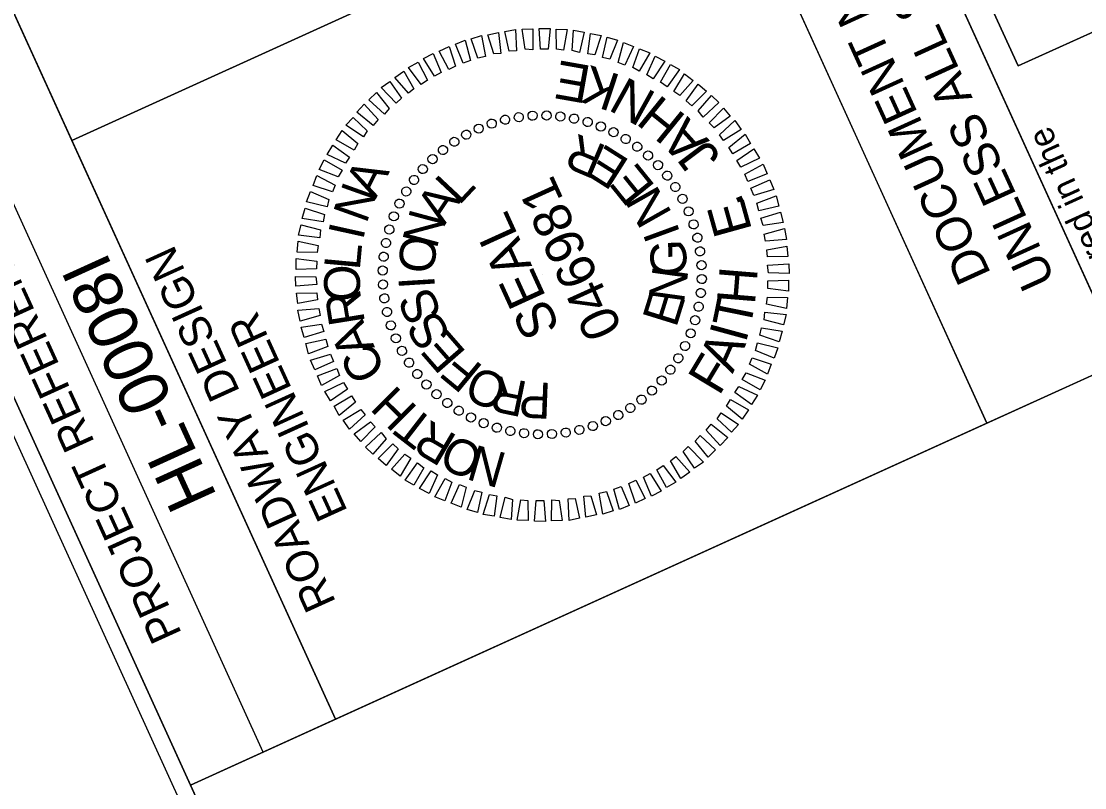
# Model space of a CAD drawing. Extents: x 2097304 to 2099003, y 683920 to 685908.
# Drawn here: x 2097390.4 to 2097557.6, y 685265 to 685385.6 of the extents above; entities that cross this region are included whole.
import ezdxf

# ---------------------------------------------------------------- set-up
doc = ezdxf.new("R2010")
doc.units = 0
for name, color, linetype in [('Sheet Block Title CELL', 7, 'Continuous'), ('Sheet Data Field CELL', 7, 'Continuous'), ('Sheet Layout Plan Border', 7, 'Continuous'), ('Sheet PE Seal Cell', 7, 'Continuous'), ('Sheet Plot Border Inside CELL', 7, 'Continuous'), ('Sheet Profile CELL', 7, 'Continuous'), ('Sheet Sticker Exception Certification CELL', 7, 'Continuous')]:
    doc.layers.add(name, color=color, linetype=linetype)

msp = doc.modelspace()

# ---------------------------------------------------------------- linework, layer by layer
at = {"layer": 'Sheet Block Title CELL'}
for points in [[(2097563.62, 685332.14), (2097480.76, 685514.24), (2097504.66, 685525.11), (2097587.51, 685343.02)], [(2097547.11, 685378.58), (2097538.59, 685397.29), (2097554.83, 685404.68), (2097563.35, 685385.97)]]:
    msp.add_lwpolyline(points, close=True, dxfattribs=at)
msp.add_lwpolyline([(2097538.59, 685397.29), (2097547.11, 685378.58), (2097563.35, 685385.97), (2097554.83, 685404.68), (2097538.59, 685397.29)], dxfattribs=at)
at = {"layer": 'Sheet Layout Plan Border'}
msp.add_lwpolyline([(2098911.14, 684517.12), (2097955.44, 684082.23), (2097417.03, 685265.44), (2097587.51, 685343.02), (2097536.86, 685454.34), (2098323.16, 685809.28)], close=True, dxfattribs=at)
at = {"layer": 'Sheet PE Seal Cell'}
for p, q in [((2097468.61, 685370.57), (2097468.61, 685370.57)), ((2097470.81, 685370.8), (2097470.81, 685370.8)), ((2097473, 685370.81), (2097473, 685370.81)), ((2097475.19, 685370.7), (2097475.19, 685370.7)), ((2097477.35, 685370.31), (2097477.35, 685370.31)), ((2097462.34, 685368.76), (2097462.34, 685368.76)), ((2097464.41, 685369.53), (2097464.41, 685369.53)), ((2097466.51, 685370.1), (2097466.51, 685370.1)), ((2097479.5, 685369.81), (2097479.5, 685369.81)), ((2097481.53, 685369.08), (2097481.53, 685369.08)), ((2097460.36, 685367.8), (2097460.36, 685367.8)), ((2097483.58, 685368.2), (2097483.58, 685368.2)), ((2097485.44, 685367.13), (2097485.44, 685367.13)), ((2097456.69, 685365.36), (2097456.69, 685365.36)), ((2097458.53, 685366.64), (2097458.53, 685366.64)), ((2097487.28, 685365.88), (2097487.28, 685365.88)), ((2097455.03, 685363.95), (2097455.03, 685363.95)), ((2097488.99, 685364.52), (2097488.99, 685364.52)), ((2097453.54, 685362.39), (2097453.54, 685362.39)), ((2097490.55, 685363.03), (2097490.55, 685363.03)), ((2097452.18, 685360.67), (2097452.18, 685360.67)), ((2097491.97, 685361.36), (2097491.97, 685361.36)), ((2097450.93, 685358.84), (2097450.93, 685358.84)), ((2097493.24, 685359.53), (2097493.24, 685359.53)), ((2097449.85, 685356.98), (2097449.85, 685356.98)), ((2097494.41, 685357.69), (2097494.41, 685357.69)), ((2097495.36, 685355.71), (2097495.36, 685355.71)), ((2097448.97, 685354.93), (2097448.97, 685354.93)), ((2097496.14, 685353.65), (2097496.14, 685353.65)), ((2097448.25, 685352.9), (2097448.25, 685352.9)), ((2097447.74, 685350.74), (2097447.74, 685350.74)), ((2097496.71, 685351.55), (2097496.71, 685351.55)), ((2097447.35, 685348.59), (2097447.35, 685348.59)), ((2097497.17, 685349.45), (2097497.17, 685349.45)), ((2097497.4, 685347.25), (2097497.4, 685347.25)), ((2097447.25, 685346.4), (2097447.25, 685346.4)), ((2097472.33, 685345.73), (2097472.33, 685345.73)), ((2097447.26, 685344.21), (2097447.26, 685344.21)), ((2097497.41, 685345.05), (2097497.41, 685345.05)), ((2097447.49, 685342), (2097447.49, 685342)), ((2097497.31, 685342.86), (2097497.31, 685342.86)), ((2097496.92, 685340.71), (2097496.92, 685340.71)), ((2097447.95, 685339.91), (2097447.95, 685339.91)), ((2097496.41, 685338.56), (2097496.41, 685338.56)), ((2097448.52, 685337.8), (2097448.52, 685337.8)), ((2097449.3, 685335.74), (2097449.3, 685335.74)), ((2097495.69, 685336.52), (2097495.69, 685336.52)), ((2097450.25, 685333.76), (2097450.25, 685333.76)), ((2097494.81, 685334.48), (2097494.81, 685334.48)), ((2097451.42, 685331.93), (2097451.42, 685331.93)), ((2097493.73, 685332.61), (2097493.73, 685332.61)), ((2097492.48, 685330.78), (2097492.48, 685330.78)), ((2097452.69, 685330.09), (2097452.69, 685330.09)), ((2097491.12, 685329.06), (2097491.12, 685329.06)), ((2097454.11, 685328.43), (2097454.11, 685328.43)), ((2097455.67, 685326.94), (2097455.67, 685326.94)), ((2097489.63, 685327.51), (2097489.63, 685327.51)), ((2097457.38, 685325.58), (2097457.38, 685325.58)), ((2097487.97, 685326.09), (2097487.97, 685326.09)), ((2097459.22, 685324.32), (2097459.22, 685324.32)), ((2097484.3, 685323.65), (2097484.3, 685323.65)), ((2097486.13, 685324.81), (2097486.13, 685324.81)), ((2097461.08, 685323.25), (2097461.08, 685323.25)), ((2097463.13, 685322.37), (2097463.13, 685322.37)), ((2097480.25, 685321.92), (2097480.25, 685321.92)), ((2097482.32, 685322.69), (2097482.32, 685322.69)), ((2097465.16, 685321.64), (2097465.16, 685321.64)), ((2097467.31, 685321.14), (2097467.31, 685321.14)), ((2097469.47, 685320.75), (2097469.47, 685320.75)), ((2097471.66, 685320.65), (2097471.66, 685320.65)), ((2097473.85, 685320.65), (2097473.85, 685320.65)), ((2097476.05, 685320.89), (2097476.05, 685320.89)), ((2097478.15, 685321.35), (2097478.15, 685321.35))]:
    msp.add_line(p, q, dxfattribs=at)
for points in [[(2097464.7, 685380.49), (2097463.78, 685383.47), (2097465.47, 685383.86), (2097465.82, 685380.56)], [(2097467.15, 685380.89), (2097466.46, 685383.98), (2097468.11, 685384.34), (2097468.27, 685380.96)], [(2097469.65, 685381.2), (2097469.18, 685384.39), (2097470.86, 685384.44), (2097470.83, 685381.13)], [(2097472.06, 685381.2), (2097471.83, 685384.5), (2097473.55, 685384.46), (2097473.27, 685381.2)], [(2097474.57, 685381.24), (2097474.53, 685384.36), (2097476.25, 685384.31), (2097475.68, 685381.09)], [(2097477.02, 685381.04), (2097477.23, 685384.21), (2097478.92, 685383.88), (2097478.18, 685380.69)], [(2097479.47, 685380.5), (2097479.9, 685383.67), (2097481.61, 685383.4), (2097480.6, 685380.31)], [(2097459.92, 685379.03), (2097458.67, 685382.03), (2097460.21, 685382.62), (2097461.06, 685379.43)], [(2097462.21, 685379.79), (2097461.16, 685382.83), (2097462.79, 685383.35), (2097463.41, 685380.06)], [(2097481.82, 685379.93), (2097482.51, 685383.1), (2097484.15, 685382.64), (2097482.93, 685379.66)], [(2097484.27, 685379.12), (2097485.08, 685382.29), (2097486.65, 685381.63), (2097485.33, 685378.72)], [(2097455.37, 685376.96), (2097453.66, 685379.75), (2097455.17, 685380.54), (2097456.42, 685377.55)], [(2097457.63, 685378.04), (2097456.14, 685380.93), (2097457.69, 685381.64), (2097458.72, 685378.54)], [(2097486.55, 685378.34), (2097487.64, 685381.26), (2097489.23, 685380.66), (2097487.58, 685377.77)], [(2097453.31, 685375.69), (2097451.33, 685378.36), (2097452.81, 685379.2), (2097454.32, 685376.37)], [(2097488.79, 685377.17), (2097490.08, 685380.12), (2097491.6, 685379.32), (2097489.77, 685376.57)], [(2097490.94, 685376.06), (2097492.49, 685378.8), (2097493.9, 685378.01), (2097491.94, 685375.3)], [(2097451.31, 685374.29), (2097449.14, 685376.76), (2097450.57, 685377.74), (2097452.15, 685374.99)], [(2097492.99, 685374.57), (2097494.68, 685377.37), (2097496.05, 685376.3), (2097493.93, 685373.96)], [(2097449.38, 685372.75), (2097447.01, 685375.18), (2097448.38, 685376.14), (2097450.19, 685373.5)], [(2097494.97, 685373.11), (2097496.86, 685375.73), (2097498.14, 685374.61), (2097495.84, 685372.3)], [(2097447.52, 685371.02), (2097445.08, 685373.26), (2097446.26, 685374.4), (2097448.27, 685371.91)], [(2097496.84, 685371.54), (2097498.94, 685373.93), (2097500.11, 685372.81), (2097497.63, 685370.53)], [(2097445.76, 685369.23), (2097443.17, 685371.3), (2097444.36, 685372.55), (2097446.55, 685370.14)], [(2097444.22, 685367.43), (2097441.46, 685369.25), (2097442.6, 685370.49), (2097444.83, 685368.37)], [(2097498.58, 685369.65), (2097500.83, 685371.94), (2097501.89, 685370.71), (2097499.33, 685368.84)], [(2097500.17, 685367.73), (2097502.6, 685369.99), (2097503.62, 685368.59), (2097500.83, 685366.88)], [(2097442.75, 685365.34), (2097439.92, 685366.96), (2097440.9, 685368.45), (2097443.37, 685366.39)], [(2097501.66, 685365.77), (2097504.24, 685367.83), (2097505.06, 685366.39), (2097502.29, 685364.74)], [(2097441.42, 685363.3), (2097438.5, 685364.66), (2097439.42, 685366.13), (2097442.04, 685364.24)], [(2097502.93, 685363.71), (2097505.61, 685365.54), (2097506.5, 685364.08), (2097503.56, 685362.68)], [(2097440.27, 685361.13), (2097437.27, 685362.29), (2097438.06, 685363.81), (2097440.89, 685362.18)], [(2097504.19, 685361.54), (2097507.05, 685363.12), (2097507.68, 685361.59), (2097504.64, 685360.43)], [(2097439.36, 685358.79), (2097436.33, 685359.78), (2097436.92, 685361.37), (2097439.77, 685359.81)], [(2097505.14, 685359.34), (2097508.1, 685360.68), (2097508.73, 685359.16), (2097505.59, 685358.22)], [(2097438.51, 685356.43), (2097435.29, 685357.22), (2097435.89, 685358.81), (2097438.8, 685357.6)], [(2097506.04, 685357), (2097509.08, 685358.16), (2097509.49, 685356.54), (2097506.35, 685355.82)], [(2097437.89, 685354.06), (2097434.62, 685354.6), (2097435.08, 685356.24), (2097438.13, 685355.21)], [(2097506.67, 685354.65), (2097509.77, 685355.57), (2097510.22, 685353.96), (2097507.03, 685353.49)], [(2097437.37, 685351.57), (2097434.01, 685351.96), (2097434.42, 685353.58), (2097437.46, 685352.82)], [(2097507.22, 685352.1), (2097510.39, 685352.99), (2097510.73, 685351.28), (2097507.43, 685351.04)], [(2097436.95, 685349.24), (2097433.8, 685349.29), (2097433.95, 685351), (2097437.1, 685350.35)], [(2097507.63, 685349.65), (2097510.76, 685350.25), (2097510.94, 685348.63), (2097507.74, 685348.55)], [(2097436.85, 685346.67), (2097433.65, 685346.58), (2097433.65, 685348.28), (2097436.9, 685347.9)], [(2097507.74, 685347.23), (2097511.08, 685347.48), (2097511.12, 685345.96), (2097507.9, 685346.03)], [(2097436.92, 685344.23), (2097433.58, 685343.97), (2097433.54, 685345.49), (2097436.76, 685345.42)], [(2097507.81, 685344.78), (2097511.01, 685344.87), (2097511.01, 685343.17), (2097507.76, 685343.56)], [(2097437.03, 685341.81), (2097433.9, 685341.2), (2097433.72, 685342.82), (2097436.92, 685342.91)], [(2097507.71, 685342.21), (2097510.86, 685342.17), (2097510.71, 685340.45), (2097507.56, 685341.1)], [(2097437.44, 685339.35), (2097434.27, 685338.46), (2097433.93, 685340.17), (2097437.23, 685340.41)], [(2097507.29, 685339.88), (2097510.65, 685339.49), (2097510.24, 685337.87), (2097507.2, 685338.63)], [(2097437.99, 685336.8), (2097434.89, 685335.89), (2097434.44, 685337.49), (2097437.63, 685337.96)], [(2097506.77, 685337.39), (2097510.04, 685336.85), (2097509.58, 685335.21), (2097506.53, 685336.24)], [(2097438.62, 685334.45), (2097435.58, 685333.29), (2097435.17, 685334.91), (2097438.31, 685335.63)], [(2097506.15, 685335.02), (2097509.37, 685334.23), (2097508.77, 685332.64), (2097505.86, 685333.85)], [(2097439.52, 685332.12), (2097436.56, 685330.77), (2097435.92, 685332.29), (2097439.07, 685333.23)], [(2097505.3, 685332.66), (2097508.33, 685331.68), (2097507.74, 685330.09), (2097504.89, 685331.65)], [(2097440.47, 685329.91), (2097437.61, 685328.34), (2097436.98, 685329.86), (2097440.02, 685331.02)], [(2097504.39, 685330.32), (2097507.39, 685329.16), (2097506.6, 685327.64), (2097503.77, 685329.27)], [(2097441.73, 685327.74), (2097439.05, 685325.91), (2097438.16, 685327.38), (2097441.1, 685328.77)], [(2097503.24, 685328.15), (2097506.16, 685326.79), (2097505.24, 685325.32), (2097502.62, 685327.21)], [(2097443, 685325.68), (2097440.42, 685323.62), (2097439.6, 685325.06), (2097442.37, 685326.71)], [(2097501.91, 685326.12), (2097504.74, 685324.49), (2097503.76, 685323), (2097501.29, 685325.06)], [(2097444.49, 685323.72), (2097442.06, 685321.46), (2097441.04, 685322.86), (2097443.83, 685324.57)], [(2097500.44, 685324.02), (2097503.2, 685322.2), (2097502.06, 685320.96), (2097499.83, 685323.08)], [(2097446.08, 685321.81), (2097443.83, 685319.52), (2097442.77, 685320.74), (2097445.33, 685322.62)], [(2097498.9, 685322.22), (2097501.49, 685320.16), (2097500.3, 685318.9), (2097498.11, 685321.31)], [(2097447.82, 685319.91), (2097445.72, 685317.52), (2097444.55, 685318.64), (2097447.03, 685320.92)], [(2097497.14, 685320.43), (2097499.58, 685318.19), (2097498.4, 685317.05), (2097496.39, 685319.54)], [(2097449.69, 685318.34), (2097447.8, 685315.72), (2097446.52, 685316.84), (2097448.82, 685319.15)], [(2097495.28, 685318.71), (2097497.65, 685316.27), (2097496.28, 685315.31), (2097494.47, 685317.95)], [(2097451.67, 685316.88), (2097449.98, 685314.08), (2097448.61, 685315.16), (2097450.73, 685317.5)], [(2097493.35, 685317.17), (2097495.52, 685314.69), (2097494.09, 685313.71), (2097492.51, 685316.46)], [(2097453.72, 685315.39), (2097452.17, 685312.65), (2097450.76, 685313.44), (2097452.72, 685316.15)], [(2097491.35, 685315.76), (2097493.33, 685313.09), (2097491.85, 685312.25), (2097490.34, 685315.08)], [(2097455.87, 685314.29), (2097454.58, 685311.34), (2097453.06, 685312.13), (2097454.89, 685314.88)], [(2097458.11, 685313.11), (2097457.02, 685310.19), (2097455.43, 685310.79), (2097457.08, 685313.68)], [(2097489.29, 685314.49), (2097491, 685311.7), (2097489.49, 685310.91), (2097488.24, 685313.91)], [(2097460.39, 685312.33), (2097459.58, 685309.16), (2097458.01, 685309.82), (2097459.33, 685312.73)], [(2097462.84, 685311.53), (2097462.15, 685308.35), (2097460.51, 685308.81), (2097461.73, 685311.79)], [(2097484.74, 685312.42), (2097485.99, 685309.42), (2097484.45, 685308.83), (2097483.6, 685312.02)], [(2097487.03, 685313.41), (2097488.52, 685310.52), (2097486.97, 685309.81), (2097485.94, 685312.92)], [(2097465.19, 685310.95), (2097464.76, 685307.79), (2097463.05, 685308.05), (2097464.06, 685311.15)], [(2097467.64, 685310.41), (2097467.43, 685307.24), (2097465.74, 685307.57), (2097466.48, 685310.77)], [(2097470.09, 685310.21), (2097470.13, 685307.1), (2097468.41, 685307.14), (2097468.98, 685310.36)], [(2097472.6, 685310.25), (2097472.83, 685306.95), (2097471.11, 685306.99), (2097471.39, 685310.25)], [(2097475.01, 685310.25), (2097475.48, 685307.06), (2097473.8, 685307.01), (2097473.83, 685310.32)], [(2097477.51, 685310.56), (2097478.2, 685307.47), (2097476.55, 685307.11), (2097476.39, 685310.49)], [(2097479.96, 685310.97), (2097480.88, 685307.98), (2097479.19, 685307.59), (2097478.84, 685310.89)], [(2097482.45, 685311.66), (2097483.5, 685308.62), (2097481.87, 685308.1), (2097481.25, 685311.39)]]:
    msp.add_lwpolyline(points, close=True, dxfattribs=at)
for centre, major_axis in [((2097464.39, 685369.51), (-0.228, 0.683)), ((2097466.49, 685370.12), (-0.168, 0.7)), ((2097468.64, 685370.53), (-0.106, 0.712)), ((2097470.81, 685370.76), (-0.044, 0.719)), ((2097473, 685370.8), (0.019, 0.72)), ((2097475.18, 685370.64), (0.082, 0.715)), ((2097477.34, 685370.3), (0.144, 0.705)), ((2097479.47, 685369.77), (0.205, 0.69)), ((2097460.38, 685367.77), (-0.343, 0.633)), ((2097462.34, 685368.73), (-0.287, 0.66)), ((2097481.54, 685369.06), (0.264, 0.67)), ((2097483.53, 685368.16), (0.322, 0.644)), ((2097458.5, 685366.65), (-0.397, 0.601)), ((2097485.45, 685367.1), (0.377, 0.614)), ((2097456.73, 685365.36), (-0.448, 0.564)), ((2097487.26, 685365.88), (0.429, 0.579)), ((2097488.96, 685364.5), (0.477, 0.539)), ((2097455.08, 685363.93), (-0.495, 0.523)), ((2097490.53, 685362.98), (0.523, 0.495)), ((2097453.56, 685362.36), (-0.539, 0.477)), ((2097491.97, 685361.33), (0.564, 0.448)), ((2097452.18, 685360.66), (-0.579, 0.429)), ((2097493.25, 685359.56), (0.601, 0.397)), ((2097450.95, 685358.84), (-0.614, 0.377)), ((2097449.89, 685356.93), (-0.644, 0.322)), ((2097494.38, 685357.68), (0.633, 0.343)), ((2097449, 685354.93), (-0.67, 0.264)), ((2097495.34, 685355.71), (0.66, 0.287)), ((2097448.29, 685352.86), (-0.69, 0.205)), ((2097496.12, 685353.67), (0.683, 0.228)), ((2097496.72, 685351.57), (0.7, 0.168)), ((2097447.76, 685350.74), (-0.705, 0.144)), ((2097447.41, 685348.58), (-0.715, 0.082)), ((2097497.14, 685349.42), (0.712, 0.106)), ((2097447.26, 685346.4), (-0.72, 0.019)), ((2097497.36, 685347.24), (0.719, 0.044)), ((2097497.4, 685345.06), (0.72, -0.019)), ((2097447.3, 685344.21), (-0.719, -0.044)), ((2097497.25, 685342.87), (0.715, -0.082)), ((2097447.52, 685342.03), (-0.712, -0.106)), ((2097447.94, 685339.89), (-0.7, -0.168)), ((2097496.9, 685340.71), (0.705, -0.144)), ((2097448.54, 685337.78), (-0.683, -0.228)), ((2097496.37, 685338.59), (0.69, -0.205)), ((2097495.66, 685336.52), (0.67, -0.264)), ((2097449.32, 685335.74), (-0.66, -0.287)), ((2097494.77, 685334.52), (0.644, -0.322)), ((2097450.28, 685333.77), (-0.633, -0.343)), ((2097451.41, 685331.9), (-0.601, -0.397)), ((2097493.71, 685332.61), (0.614, -0.377)), ((2097452.69, 685330.12), (-0.564, -0.448)), ((2097492.48, 685330.8), (0.579, -0.429)), ((2097454.13, 685328.47), (-0.523, -0.495)), ((2097491.1, 685329.1), (0.539, -0.477)), ((2097455.7, 685326.95), (-0.477, -0.539)), ((2097487.93, 685326.09), (0.448, -0.564)), ((2097489.58, 685327.52), (0.495, -0.523)), ((2097457.4, 685325.57), (-0.429, -0.579)), ((2097459.21, 685324.35), (-0.377, -0.614)), ((2097486.16, 685324.8), (0.397, -0.601)), ((2097461.13, 685323.29), (-0.322, -0.644)), ((2097482.32, 685322.72), (0.287, -0.66)), ((2097484.28, 685323.68), (0.343, -0.633)), ((2097463.12, 685322.4), (-0.264, -0.67)), ((2097465.19, 685321.68), (-0.205, -0.69)), ((2097467.32, 685321.15), (-0.144, -0.705)), ((2097478.17, 685321.34), (0.168, -0.7)), ((2097480.27, 685321.94), (0.228, -0.683)), ((2097469.48, 685320.81), (-0.082, -0.715)), ((2097471.66, 685320.65), (-0.019, -0.72)), ((2097473.85, 685320.69), (0.044, -0.719)), ((2097476.02, 685320.92), (0.106, -0.712))]:
    msp.add_ellipse(centre, major_axis=major_axis, ratio=0.999708, dxfattribs=at)
at = {"layer": 'Sheet Plot Border Inside CELL'}
msp.add_lwpolyline([(2098977.25, 684378), (2098287.02, 685894.84), (2097326.67, 685457.85), (2098016.9, 683941)], close=True, dxfattribs=at)
at = {"layer": 'Sheet Profile CELL'}
for p, q in [((2097428.45, 685270.64), (2097345.6, 685452.72)), ((2097398.39, 685366.88), (2097500.74, 685413.46))]:
    msp.add_line(p, q, dxfattribs=at)
for points in [[(2097334.17, 685447.53), (2097955.44, 684082.23), (2098911.14, 684517.12), (2098289.88, 685882.41)], [(2097398.39, 685366.88), (2097356.97, 685457.9), (2097459.37, 685504.5), (2097500.79, 685413.48)], [(2097417.03, 685265.44), (2097334.17, 685447.53), (2097356.97, 685457.9), (2097439.83, 685275.82)], [(2097439.83, 685275.82), (2097398.39, 685366.88), (2097500.79, 685413.48), (2097542.23, 685322.41)]]:
    msp.add_lwpolyline(points, close=True, dxfattribs=at)
at = {"layer": 'Sheet Sticker Exception Certification CELL'}
for p, q in [((2097480.77, 685514.22), (2097563.62, 685332.14)), ((2097542.23, 685322.41), (2097459.38, 685504.48)), ((2097563.62, 685332.14), (2097542.23, 685322.41))]:
    msp.add_line(p, q, dxfattribs=at)

# ---------------------------------------------------------------- texts
at = {"layer": 'Sheet Block Title CELL'}
msp.add_text('Prepared in the ', height=4.0012, rotation=114.4674, dxfattribs=at).set_placement((2097567.23, 685336.12))
at = {"layer": 'Sheet Data Field CELL'}
msp.add_text('HL-0008I', height=7.75, rotation=114.4674, dxfattribs=at).set_placement((2097421.29, 685310.85))
at = {"layer": 'Sheet PE Seal Cell'}
for s, height, rotation, p in [('E', 6, 169.9604, (2097480.24, 685378.55)), ('K', 6, 161.6765, (2097484.88, 685377.07)), ('N', 6, 150.9507, (2097490.5, 685374.19)), ('H', 6, 140.9667, (2097495.16, 685370.6)), ('A', 6, 132.1264, (2097498.71, 685366.8)), ('R', 5.64, 156.9488, (2097482.65, 685365.91)), ('E', 5.64, 147.5915, (2097486.26, 685363.65)), ('J', 6, 126.8686, (2097500.53, 685364.29)), ('A', 5.64, 63.0846, (2097446.14, 685357.54)), ('E', 5.64, 128.8792, (2097490.23, 685359.64)), ('L', 5.64, 46.8683, (2097459.23, 685356.52)), ('046981', 5.998, 114.4674, (2097484.99, 685337.24)), ('N', 5.64, 70.2863, (2097444.67, 685353.63)), ('A', 5.64, 56.2277, (2097456.9, 685353.32)), ('N', 5.64, 119.5238, (2097492.82, 685355.38)), ('E', 6, 105.5251, (2097505.35, 685352.76)), ('.', 6, 112.6344, (2097504.23, 685356.79)), ('N', 5.64, 74.944, (2097455.71, 685349.65)), ('SEAL', 5.998, 114.4674, (2097475.2, 685337.37)), ('I', 5.64, 77.4876, (2097444.15, 685351.03)), ('I', 5.64, 110.1686, (2097494.07, 685352.27)), ('L', 5.64, 84.6883, (2097443.64, 685346.35)), ('O', 5.64, 84.3009, (2097455.28, 685345.77)), ('G', 5.64, 91.4577, (2097495.06, 685345.52)), ('O', 5.64, 91.8886, (2097443.78, 685341.58)), ('N', 5.64, 82.1014, (2097494.58, 685341.13)), ('H', 6, 85.3408, (2097505.75, 685340.93)), ('I', 5.64, 93.657, (2097455.47, 685343.66)), ('R', 5.64, 99.0885, (2097444.49, 685338.22)), ('S', 5.64, 112.3678, (2097456.62, 685339.45)), ('E', 5.64, 72.7443, (2097493.37, 685337.28)), ('T', 6, 78.5405, (2097504.95, 685337.01)), ('A', 5.64, 113.4877, (2097446.05, 685334.31)), ('S', 5.64, 121.723, (2097458.15, 685336.2)), ('E', 5.64, 131.0785, (2097460.54, 685333.49)), ('I', 6, 74.7386, (2097504.3, 685334.86)), ('A', 6, 65.8983, (2097502.25, 685330.08)), ('C', 5.64, 120.6873, (2097447.95, 685330.84)), ('F', 6, 58.8817, (2097500.11, 685326.54)), ('F', 5.64, 140.4344, (2097463.23, 685331.2)), ('O', 5.64, 159.1487, (2097467.28, 685329.42)), ('R', 5.64, 168.5071, (2097470.23, 685328.84)), ('P', 5.64, 177.8663, (2097473.81, 685328.71)), ('H', 5.64, 135.0869, (2097452.92, 685324.75)), ('T', 5.64, 142.2872, (2097455.77, 685322.48)), ('R', 5.64, 149.4879, (2097459.18, 685320.3)), ('O', 5.64, 156.6892, (2097463.43, 685318.44)), ('N', 5.64, 163.8909, (2097467.02, 685317.55))]:
    msp.add_text(s, height=height, rotation=rotation, dxfattribs=at).set_placement(p)
at = {"layer": 'Sheet Profile CELL'}
for s, height, p in [('PROJECT REFERENCE NO.', 5.0001, (2097415.74, 685289.26)), ('ROADWAY DESIGN', 5.0001, (2097439.97, 685294.19)), ('ENGINEER', 5, (2097441.81, 685308.49))]:
    msp.add_text(s, height=height, rotation=114.4674, dxfattribs=at).set_placement(p)
at = {"layer": 'Sheet Sticker Exception Certification CELL'}
for s, p in [('UNLESS ALL SIGNATURES COMPLETED', (2097553.03, 685344.9)), ('DOCUMENT NOT CONSIDERED FINAL', (2097542.92, 685345.87))]:
    msp.add_text(s, height=5.5, rotation=114.4674, dxfattribs=at).set_placement(p)

doc.saveas('drawing.dxf')
